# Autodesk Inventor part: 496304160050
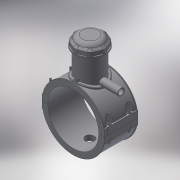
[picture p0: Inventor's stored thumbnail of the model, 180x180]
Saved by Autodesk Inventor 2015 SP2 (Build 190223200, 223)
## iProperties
Created: 2017-07
Part Number: 496304160050
Material: Generic
Description: PLASSON TAPPING SADDLE 160x50
Document SubType Name: Modeling
Designer: KIM
Mass: 1086.48 g
Surface Area: 2505.43 cm^2
Volume: 1086.48 cm^3
Density: 1 g/cm^3
Appearance: Default
Author: KIM
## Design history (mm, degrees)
derived "496304.ipt"
feature "Solid1::496304.ipt"
feature "Solid2::496304.ipt"
feature "Solid4::496304.ipt"
feature "Solid5::496304.ipt"
tag "TaggingFeature1"
body "Solid1"
body "Solid2"
other parameters: "B_" = 199, "L_" = 118, "d_t" = 6, "H_2" = 138, "H_1" = 24, "H_" = 175, "d1" = 182.4, "d148" = 2.4, "d160" = 2.4, "d169" = 3.375, "d192" = 6.3, "d2" = 199, "d4" = 118, "d5" = 0, "d6" = 0.1, "d8" = 0, "d19" = 6, "d20" = 6, "d21" = 70.8, "d23" = 0, "d24" = 35.4, "d26" = 0, "d29" = 3, "d30" = 53.33333, "d31" = 6, "d32" = 0, "d33" = 0, "d34" = 0.6, "d40" = 94.848, "d41" = 72, "d43" = 0, "d45" = 0, "d47" = 162, "d70" = 15, "d72" = 0, "d73" = 6, "d75" = 5, "d76" = 0, "d77" = 8, "d79" = 15, "d80" = 47.2, "d82" = 5 deg, "d84" = 4, "d85" = 14, "d86" = 0, "d87" = 3, "d88" = 0, "d89" = 1, "d90" = 1, "d91" = 94.4, "d92" = 0, "d93" = 0.5, "d94" = 84.21053, "d96" = 186.048, "d97" = 2.36, "d98" = 0, "d102" = 1.6, "d120" = 140 deg, "d121" = 24.228, "d122" = 20 deg, "d123" = 364.8, "d124" = 109.44, "d126" = 0, "d143" = 164.8, "d145" = 17.23077, "d149" = 2.4, "d150" = 18.95385, "d153" = 118, "d154" = 0, "d156" = 91.2, "d157" = 160 deg, "d159" = 4.48, "d161" = 2.4, "d162" = 70.8, "d163" = 0, "d167" = 16, "d168" = 88.97561, "d170" = 3.375, "d172" = 0, "d173" = 1, "d176" = 20 deg, "d177" = 11.2, "d178" = 22.4, "d180" = 0, "d183" = 8.96, "d184" = 8.96, "d185" = 38.35, "d186" = 38.35, "d187" = 91.2, "d188" = 6.72, "d189" = 11.2, "d190" = 0, "d191" = 136.8, "d193" = 6.3, "d194" = 4.13, "d195" = 90 deg, "d197" = 0, "d199" = 0, "d200" = 11.2, "d202" = 0, "d203" = 138, "d204" = 68.4, "d205" = 50.4, "d206" = 61.2, "d207" = 103.5, "d208" = 107.64, "d209" = 128.34, "d210" = 61.92, "d211" = 72, "d212" = 57.6, "d213" = -0.9, "d216" = 0, "d217" = 16, "d218" = 16, "d219" = 3.2, "d224" = 0, "d230" = 3.2, "d233" = 6, "d236" = 99.5, "d237" = 35.4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
